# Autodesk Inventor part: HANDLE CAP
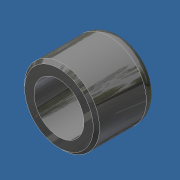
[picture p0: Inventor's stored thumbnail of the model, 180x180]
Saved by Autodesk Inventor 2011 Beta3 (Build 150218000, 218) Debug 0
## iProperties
Shininess: 64.0
Length Units: 11272
Angle Units: 11279
Time Units: 11290
Mass Units: 11286
Length Display Precision: 3
Angle Display Precision: 2
Compacted: True
Part Number: HANDLE CAP
Document SubType Name: Modeling
Created: 2003-11
Designer: Autodesk, Inc.
Manufacturer: Standard
Standards Organization: Custom
Mass: 2.20956 g
Surface Area: 17.857 cm^2
Volume: 2.37587 cm^3
Density: 0.93 g/cm^3
Material: Rubber
Density: 0.0
Volumn: 0.0
Area: 0.0
PropertySet Name: Model Information
Control State: 0
Master: False
Checked Out: False
Author: Autodesk, Inc.
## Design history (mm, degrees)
sketch "Sketch1"
  geometry: C1 r 9.525 at (0, 0); C2 r 6.35 at (0, 0); 1 further point
  constraints: 2 centre point, 2 coincident
  dimensions: "d0" = 19.05 diameter of C1; "d1" = 12.7 diameter of C2
extrude "Extrusion1" new body sketch "Sketch1" distance "d2" = 15.875; taper "d3" = 0 deg
chamfer "Chamfer1" distance "d5" = 0.7874; stored, may be unused: second distance "d6" = 3.175, angle "d7" = 45 deg
fillet "Fillet2" dims "d8" = 3.175
body "Solid1"
